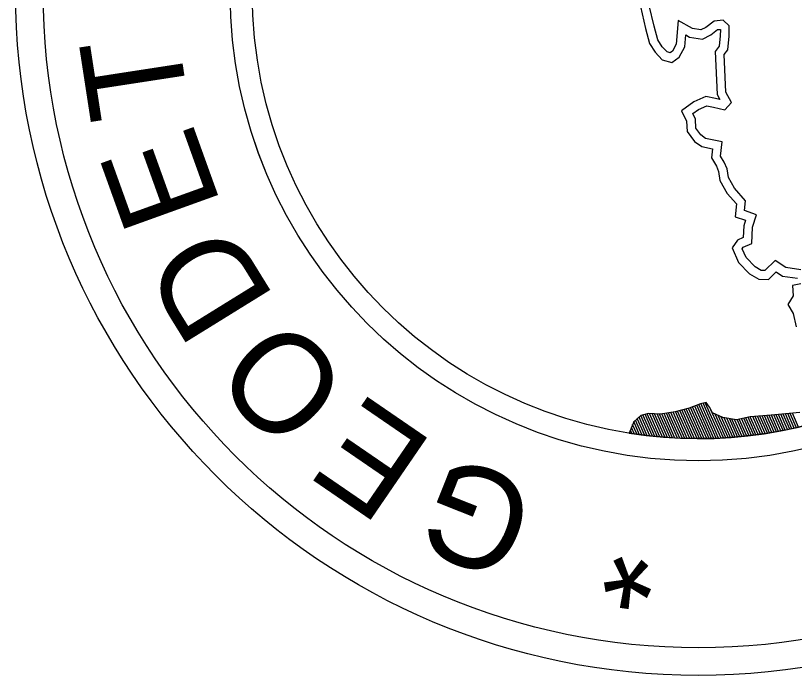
# Model space of a CAD drawing. Extents: x -755061 to -754557, y -1162352 to -1161657.
# Drawn here: x -754703.17 to -754694.38, y -1161790.32 to -1161782.87 of the extents above; entities that cross this region are included whole.
import ezdxf

# ---------------------------------------------------------------- set-up
doc = ezdxf.new("R2010")
doc.units = 0
doc.layers.add('Popisove_pole', color=7, linetype='Continuous')

msp = doc.modelspace()

# ---------------------------------------------------------------- linework, layer by layer
at = {"layer": 'Popisove_pole'}
for p, q in [((-754695.4757, -1161787.6428), (-754695.622, -1161787.3134)), ((-754695.4484, -1161787.6428), (-754695.5974, -1161787.3072)), ((-754695.4211, -1161787.6426), (-754695.5728, -1161787.3011)), ((-754695.3938, -1161787.6424), (-754695.5491, -1161787.2929)), ((-754695.3667, -1161787.6419), (-754695.5258, -1161787.2837)), ((-754695.3396, -1161787.6414), (-754695.5025, -1161787.2745)), ((-754695.3125, -1161787.6406), (-754695.4792, -1161787.2654)), ((-754695.2856, -1161787.6398), (-754695.456, -1161787.2562)), ((-754695.2587, -1161787.6388), (-754695.4324, -1161787.2476)), ((-754695.2318, -1161787.6376), (-754695.4074, -1161787.2423)), ((-754695.205, -1161787.6363), (-754695.3824, -1161787.237)), ((-754695.1783, -1161787.6349), (-754695.3186, -1161787.319)), ((-754696.0376, -1161787.6096), (-754696.131, -1161787.3993)), ((-754696.0088, -1161787.6128), (-754696.1113, -1161787.3821)), ((-754695.9801, -1161787.6159), (-754696.087, -1161787.3751)), ((-754695.9514, -1161787.6188), (-754696.0628, -1161787.3682)), ((-754695.9229, -1161787.6215), (-754696.0385, -1161787.3612)), ((-754695.8944, -1161787.624), (-754696.0125, -1161787.3581)), ((-754695.866, -1161787.6264), (-754695.9843, -1161787.36)), ((-754695.8376, -1161787.6286), (-754695.9561, -1161787.362)), ((-754695.8094, -1161787.6307), (-754695.9278, -1161787.364)), ((-754695.7812, -1161787.6326), (-754695.8996, -1161787.366)), ((-754695.7531, -1161787.6343), (-754695.873, -1161787.3643)), ((-754695.725, -1161787.6358), (-754695.8476, -1161787.3599)), ((-754695.697, -1161787.6372), (-754695.8221, -1161787.3556)), ((-754695.6691, -1161787.6385), (-754695.7967, -1161787.3512)), ((-754695.6413, -1161787.6395), (-754695.7713, -1161787.3469)), ((-754695.6135, -1161787.6405), (-754695.7459, -1161787.3426)), ((-754695.5858, -1161787.6412), (-754695.7206, -1161787.3379)), ((-754695.5582, -1161787.6418), (-754695.6959, -1161787.3318)), ((-754695.5307, -1161787.6423), (-754695.6713, -1161787.3257)), ((-754695.5032, -1161787.6426), (-754695.6467, -1161787.3195)), ((-754695.1517, -1161787.6333), (-754695.2702, -1161787.3664)), ((-754695.1251, -1161787.6316), (-754695.2361, -1161787.3816)), ((-754695.0985, -1161787.6298), (-754695.202, -1161787.3968)), ((-754695.072, -1161787.6278), (-754695.1701, -1161787.407)), ((-754694.8364, -1161787.6041), (-754694.9241, -1161787.4066)), ((-754694.8105, -1161787.6008), (-754694.8992, -1161787.4012)), ((-754694.7847, -1161787.5973), (-754694.8742, -1161787.3959)), ((-754694.7589, -1161787.5938), (-754694.8477, -1161787.3939)), ((-754694.7332, -1161787.5901), (-754694.8212, -1161787.392)), ((-754694.7075, -1161787.5863), (-754694.7947, -1161787.39)), ((-754694.6819, -1161787.5824), (-754694.7682, -1161787.388)), ((-754694.6564, -1161787.5783), (-754694.7417, -1161787.3861)), ((-754694.6309, -1161787.5741), (-754694.7152, -1161787.3841)), ((-754694.6054, -1161787.5698), (-754694.6888, -1161787.3822)), ((-754694.58, -1161787.5654), (-754694.6623, -1161787.3802)), ((-754694.5547, -1161787.5608), (-754694.6358, -1161787.3782)), ((-754694.5294, -1161787.5561), (-754694.6096, -1161787.3757)), ((-754694.5042, -1161787.5513), (-754694.5833, -1161787.3732)), ((-754694.479, -1161787.5464), (-754694.5571, -1161787.3707)), ((-754694.4539, -1161787.5413), (-754694.5308, -1161787.3682)), ((-754694.4289, -1161787.5362), (-754694.5046, -1161787.3658)), ((-754694.4039, -1161787.5309), (-754694.4783, -1161787.3633)), ((-754694.3789, -1161787.5255), (-754694.4521, -1161787.3608)), ((-754694.354, -1161787.5199), (-754694.4258, -1161787.3583)), ((-754694.3292, -1161787.5143), (-754694.3995, -1161787.3558)), ((-754696.1904, -1161787.4514), (-754696.2419, -1161787.5818)), ((-754696.1904, -1161787.4514), (-754696.2419, -1161787.5818)), ((-754696.1535, -1161787.5949), (-754696.2031, -1161787.4834)), ((-754696.1244, -1161787.5988), (-754696.1901, -1161787.4511)), ((-754696.0954, -1161787.6026), (-754696.1704, -1161787.4338)), ((-754696.0664, -1161787.6062), (-754696.1507, -1161787.4166)), ((-754695.0456, -1161787.6257), (-754695.1406, -1161787.4118)), ((-754695.0193, -1161787.6235), (-754695.1112, -1161787.4166)), ((-754694.993, -1161787.6211), (-754695.0817, -1161787.4214)), ((-754694.9667, -1161787.6186), (-754695.0522, -1161787.4262)), ((-754694.9405, -1161787.6159), (-754695.024, -1161787.4281)), ((-754694.9144, -1161787.6132), (-754694.999, -1161787.4227)), ((-754694.8884, -1161787.6103), (-754694.9741, -1161787.4173)), ((-754694.8623, -1161787.6072), (-754694.9491, -1161787.4119)), ((-754696.2414, -1161787.5819), (-754696.2416, -1161787.5813)), ((-754696.212, -1161787.5864), (-754696.2288, -1161787.5486)), ((-754696.1827, -1161787.5907), (-754696.2159, -1161787.516))]:
    msp.add_line(p, q, dxfattribs=at)
for points in [[(-754696.1143, -1161782.7657), (-754696.0571, -1161783.011), (-754696.0125, -1161783.1825), (-754695.9472, -1161783.2812), (-754695.8686, -1161783.3654), (-754695.7611, -1161783.3972), (-754695.6774, -1161783.3361), (-754695.6127, -1161783.2199), (-754695.6024, -1161783.086), (-754695.5612, -1161783.109), (-754695.4158, -1161783.1323), (-754695.3216, -1161783.0849), (-754695.2455, -1161783.0254), (-754695.2162, -1161783.0224), (-754695.2126, -1161783.0259), (-754695.2138, -1161783.0937), (-754695.2252, -1161783.2137), (-754695.2727, -1161783.2713), (-754695.249, -1161783.7588), (-754695.2184, -1161783.8158), (-754695.2689, -1161783.8035), (-754695.3759, -1161783.7805), (-754695.5113, -1161783.8416), (-754695.6506, -1161783.941), (-754695.5935, -1161784.0603), (-754695.5888, -1161784.1742), (-754695.5042, -1161784.2873), (-754695.4201, -1161784.3465), (-754695.3013, -1161784.3712), (-754695.3136, -1161784.4746), (-754695.2577, -1161784.5683), (-754695.2318, -1161784.6258), (-754695.2178, -1161784.7278), (-754695.1362, -1161784.8749), (-754695.0318, -1161784.9932), (-754695.0447, -1161785.1375), (-754694.9283, -1161785.1781), (-754694.9471, -1161785.2391), (-754694.9537, -1161785.3727), (-754695.0198, -1161785.4015), (-754695.0796, -1161785.4875), (-754695.0059, -1161785.6562), (-754694.8832, -1161785.7834), (-754694.7785, -1161785.8443), (-754694.6707, -1161785.846), (-754694.5814, -1161785.7597), (-754694.5107, -1161785.8073), (-754694.3428, -1161785.832)], [(-754694.3043, -1161785.7366), (-754694.4737, -1161785.7117), (-754694.5927, -1161785.6316), (-754694.7105, -1161785.7453), (-754694.7508, -1161785.7447), (-754694.8209, -1161785.704), (-754694.9214, -1161785.5997), (-754694.9656, -1161785.4987), (-754694.9539, -1161785.4818), (-754694.8569, -1161785.4396), (-754694.8478, -1161785.2566), (-754694.8043, -1161785.1155), (-754694.9382, -1161785.0688), (-754694.9283, -1161784.9593), (-754695.0541, -1161784.8169), (-754695.1213, -1161784.6956), (-754695.1347, -1161784.5979), (-754695.1689, -1161784.522), (-754695.2103, -1161784.4527), (-754695.1911, -1161784.292), (-754695.3795, -1161784.2528), (-754695.4337, -1161784.2147), (-754695.4901, -1161784.1391), (-754695.4944, -1161784.0356), (-754695.5241, -1161783.9736), (-754695.4612, -1161783.9287), (-754695.3648, -1161783.8852), (-754695.2912, -1161783.901), (-754695.1638, -1161783.932), (-754695.0877, -1161783.8478), (-754695.1502, -1161783.7314), (-754695.1709, -1161783.3051), (-754695.1286, -1161783.2537), (-754695.1139, -1161783.0993), (-754695.1119, -1161782.9841), (-754695.1802, -1161782.9183), (-754695.2843, -1161782.9288), (-754695.3754, -1161783), (-754695.4319, -1161783.0285), (-754695.5279, -1161783.0131), (-754695.6902, -1161782.9224), (-754695.7107, -1161783.1904), (-754695.7541, -1161783.2683), (-754695.7802, -1161783.2873), (-754695.8141, -1161783.2773), (-754695.8684, -1161783.2191), (-754695.9199, -1161783.1412), (-754695.96, -1161782.9871), (-754696.0149, -1161782.7518)], [(-754694.3033, -1161785.8957), (-754694.396, -1161785.913), (-754694.3897, -1161786.0293), (-754694.4513, -1161786.1283), (-754694.3921, -1161786.2286), (-754694.3565, -1161786.3797)], [(-754694.3168, -1161787.348), (-754694.6392, -1161787.3785), (-754694.8747, -1161787.3959), (-754695.0311, -1161787.4296), (-754695.1843, -1161787.4047), (-754695.301, -1161787.3527), (-754695.3355, -1161787.2867), (-754695.3744, -1161787.2353), (-754695.4363, -1161787.2484), (-754695.5651, -1161787.2992), (-754695.7246, -1161787.339), (-754695.8879, -1161787.3668), (-754696.0246, -1161787.3572), (-754696.1114, -1161787.3822), (-754696.1904, -1161787.4514)]]:
    msp.add_lwpolyline(points, dxfattribs=at)
for centre, radius in [((-754695.4601, -1161782.6033), 7.7125), ((-754695.4601, -1161782.6033), 7.4), ((-754695.4601, -1161782.6033), 7.4), ((-754695.4601, -1161782.6034), 5.2894), ((-754695.4601, -1161782.6033), 5.2894), ((-754695.4601, -1161782.6034), 5.0394)]:
    msp.add_circle(centre, radius, dxfattribs=at)
msp.add_arc((-754695.4601, -1161782.6033), 5.0394, 261.0755, 38.88248, dxfattribs=at)

# ---------------------------------------------------------------- texts
for s, rotation, p in [('T', 98.74768, (-754701.2058, -1161783.9301)), ('E', 109.81408, (-754700.8443, -1161785.0083)), ('D', 121.73499, (-754700.2315, -1161786.0686)), ('O', 134.49986, (-754699.3479, -1161787.0372)), ('E', 145.56626, (-754698.4245, -1161787.701)), ('G', 158.33112, (-754697.2249, -1161788.23)), ('*', 171.96105, (-754695.8493, -1161788.4874))]:
    msp.add_text(s, height=1.125, rotation=rotation, dxfattribs=at).set_placement(p)

doc.saveas('drawing.dxf')
